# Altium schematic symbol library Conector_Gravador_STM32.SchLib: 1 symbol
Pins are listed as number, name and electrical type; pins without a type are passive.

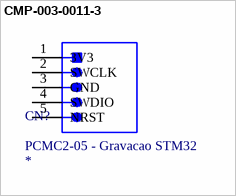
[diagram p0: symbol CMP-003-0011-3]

## CMP-003-0011-3
designator CN?, comment PCMC2-05 - Gravacao STM32
CONECTOR MACHO PARA PCI, 5 VIAS, 180 GRAUS, PASSO 2,54MM; Value: 2.54mm; Value: 250V; Value: Metaltex; Value: 3A; Value: CONN HEADER VERT 5POS 3.96MM; Value: PTH
footprint Header Macho Horizontal 5x1 - Gravacao STM32
pins: 1 3V3, 2 SWCLK, 3 GND, 4 SWDIO, 5 NRST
